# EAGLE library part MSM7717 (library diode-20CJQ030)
OKI's MSM7717-01/02/03 Single Rail CODEC Description: The MSM7717 is a single-channel CODEC CMOS IC for voice signals ranging from 300 to 3400 Hz with filters for A/D and D/A conversion. Designed especially for a single-power supply and low-power applications, the device is optimized for ISDN terminals and telephone terminals in digital wireless systems. The device uses the same transmission clocks as those used in the MSM7508B and MSM7509B. The analog output, which can drive a 1.2 kW load, can directly drive a handset receiver differentially. Features: Single power supply: 2.7 V to 3.8 V Low power consumption Operating mode: 20 mW Typ. VDD = 3 V Power-down mode: 0.03 mW Typ. VDD = 3 V Conforms to ITU-T Companding law - MSM7717-01: m/A-law pin selectable - MSM7717-02: m-law - MSM7717-03: A-law Built-in PLL eliminates a master clock Serial data rate: 64/128/256/512/1024 kHz 96/192/384/768/1536/1544/2048/200 kHz Adjustable transmit gain Adjustable receive gain Built-in reference voltage supply Please send any comments to: messi@users.sourceforge.net
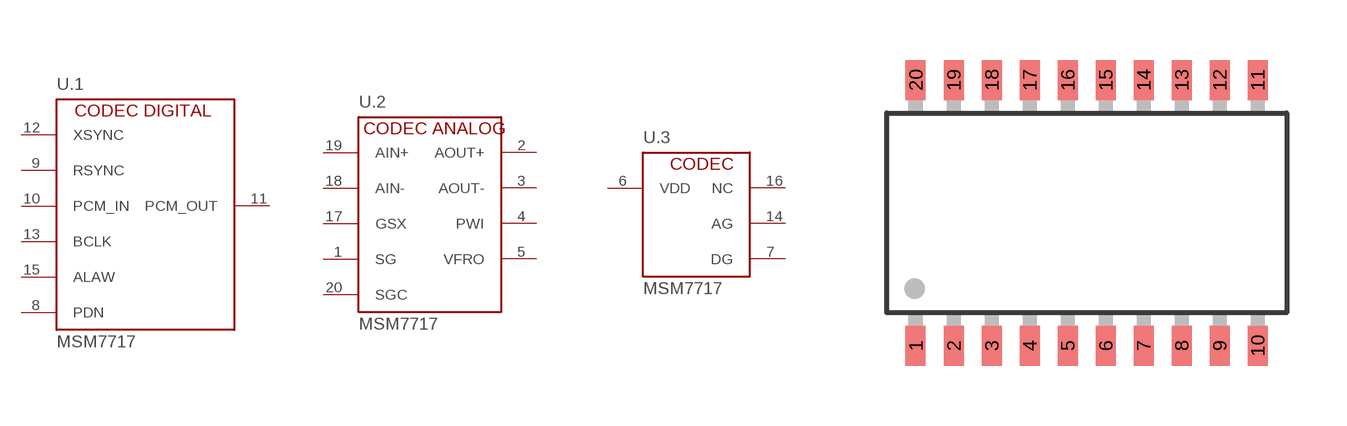
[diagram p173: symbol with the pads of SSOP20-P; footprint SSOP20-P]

Designator prefix U; gates .1=MSM7717_DIGITAL .2=MSM7717_ANALOG .3=MSM7717_PWR

## MSM7717-01  [SSOP20-P]
1  .2:SG  in
2  .2:AOUT+  out
3  .2:AOUT-  out
4  .2:PWI  out
5  .2:VFRO  out
6  .3:VDD  pwr
7  .3:DG  pwr
8  .1:PDN  in
9  .1:RSYNC  in
10  .1:PCM_IN  in
11  .1:PCM_OUT  out
12  .1:XSYNC  in
13  .1:BCLK  in
14  .3:AG  pwr
15  .1:ALAW  in
16  .3:NC  nc
17  .2:GSX  in
18  .2:AIN-  in
19  .2:AIN+  in
20  .2:SGC  in

## Footprint SSOP20-P (pad centres in mm)
SSOP20 package for the OKI 7702 and 7717
smd 0.5 x 1: 1 -4.275,-3.325; 2 -3.325,-3.325; 3 -2.375,-3.325; 4 -1.425,-3.325; 5 -0.475,-3.325; 6 0.475,-3.325; 7 1.425,-3.325; 8 2.375,-3.325; 9 3.325,-3.325; 10 4.275,-3.325; 11 4.275,3.325; 12 3.325,3.325; 13 2.375,3.325; 14 1.425,3.325; 15 0.475,3.325; 16 -0.475,3.325; 17 -1.425,3.325; 18 -2.375,3.325; 19 -3.325,3.325; 20 -4.275,3.325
